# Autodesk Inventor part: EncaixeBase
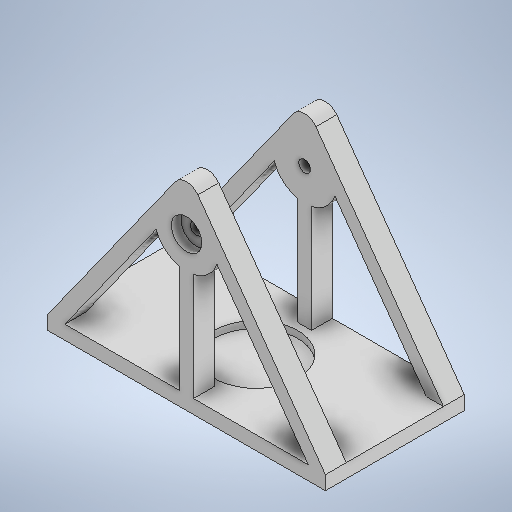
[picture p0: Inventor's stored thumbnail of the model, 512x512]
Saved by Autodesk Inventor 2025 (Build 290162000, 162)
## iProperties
Created: 2025-03
Part Number: EncaixeBase
Material: Genérico
Document SubType Name: Modeling
Designer: Ian
Density: 1 g/cm^3
Appearance: Padrão
Author: Ian
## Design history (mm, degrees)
sketch "Esboço1"
  geometry: L1 (-100, 5)-(100, 5); L2 (100, 5)-(100, -5); L3 (100, -5)-(-100, -5); L4 (-100, -5)-(-100, 5); L5 (-100, 5)-(100, -5); L6 (100, 5)-(-100, -5); 1 further point
  constraints: 12 end point, 2 midpoint, 2 parallel, 1 horizontal, 1 perpendicular
  dimensions: "d0" = 200 distance of L2.end L3.end; "d1" = 10 distance of L1.end L2.end
extrude "Extrusão1" new body sketch "Esboço1" distance "d2" = 100; taper "d3" = 0 deg
sketch "Esboço2"
  geometry: L1 (100, 5)-(-100, 5) reference; L2 (100, 5)-(-100, 5) reference; L3 (-100, -5)-(100, -5) reference; L4 (0, -5)-(0, 145); L5 (0, 145)-(-100, 5); L6 (0, 145)-(100, 5); 2 further points
  constraints: 6 end point, 2 midpoint, 1 vertical
  dimensions: "d20" = 150 distance of L4.start L4.end
extrude "Extrusão2" join sketch "Esboço2" distance "d7" = 15; taper "d8" = 0 deg
sketch "Esboço3"
  geometry: L1 (-100, 5)-(100, 5); L2 (100, -5)-(-100, -5) reference; L3 (0, -5)-(0, 145); L4 (-100, -5)-(-100, 5) reference; L5 (0, 145)-(-100, 5); L6 (0, 145)-(100, 5); 1 further point
  constraints: 8 end point, 1 midpoint, 1 vertical
  dimensions: "d21" = 150 distance of L3.start L3.end
extrude "Extrusão3" join sketch "Esboço3" distance "d9" = 15; taper "d10" = 0 deg
sketch "Esboço4"
  geometry: L1 (-100, -5)-(100, -5) reference; L2 (100, 5)-(0, 145) reference; L3 (0, 145)-(0, -5) reference; C1 r 4.25 at (0, 105); 1 further point
  constraints: 2 end point, 2 vertical, 1 centre point, 1 midpoint
  dimensions: "d13" = 8.5 diameter of C1; "d22" = 110 distance of L3.end C1.centre
extrude "Extrusão4" cut sketch "Esboço4" extent not by distance; stored distance "d14" = 0; taper "d15" = 0 deg
fillet "Arredondamento3" dims "d24" = 10
sketch "Esboço5"
  geometry: C1 r 4.25 at (0, 105) reference; C2 r 10.975 at (0, 105); 1 further point
  constraints: 1 centre point, 1 coincident
  dimensions: "d25" = 21.95 diameter of C2
extrude "Extrusão5" cut sketch "Esboço5" distance "d26" = 7; taper "d27" = 0 deg
sketch "Esboço6"
  geometry: C1 r 4.25 at (0, 105) reference; C2 r 10.975 at (0, 105); 1 further point
  constraints: 1 centre point, 1 coincident
  dimensions: "d28" = 21.95 diameter of C2
extrude "Extrusão6" cut sketch "Esboço6" distance "d29" = 7; taper "d30" = 0 deg
sketch "Esboço7"
  geometry: L1 (100, 5)-(8.137, 133.608) reference; L2 (21.886, 97.155)-(87.711, 5); L3 (100, 5)-(-100, 5) reference; L4 (87.711, 5)-(-87.711, 5); L5 (-21.886, 97.155)-(-87.711, 5); L6 (100, 5)-(8.137, 133.608) reference; L7 (-8.137, 133.608)-(-100, 5) reference; L8 (0, 105)-(0, -5.304) reference; L9 (5, 82.294)-(5, 5); L10 (-5, 82.294)-(-5, 5); C1 r 10.975 at (0, 105) reference; C2 r 4.25 at (0, 105) reference; A1 r 23.25 centre (0, 105) between (21.886, 97.155) and (-21.886, 97.155); 3 further points
  constraints: 12 end point, 4 parallel, 4 point on circle, 4 point on line, 2 vertical, 1 centre point, 1 coincident, 1 perpendicular, 1 tangent
  dimensions: "d31" = 10 distance between parallel lines of L1 L2; "d32" = 10 distance between parallel lines of L7 L5; "d39" = 5 distance between parallel lines of L9 L8; "d40" = 5 distance between parallel lines of L8 L10
extrude "Extrusão7" cut sketch "Esboço7" extent not by distance; stored distance "d33" = 0; taper "d34" = 0 deg
sketch "Esboço8"
  geometry: L1 (-200, 85)-(0, 85) reference; L2 (-108.137, -15)-(-200, -15) reference; L3 (0, 85)-(-200, 85); L4 (-200, 85)-(-200, -15); L5 (-200, -15)-(0, -15); L6 (0, -15)-(0, 85); L7 (0, 35)-(-200, 35); L8 (-100, -15)-(-100, 85); L9 (-91.863, 0)-(0, 0) reference; C1 r 30 at (-100, 35)
  constraints: 12 end point, 4 midpoint, 2 parallel, 2 perpendicular, 1 centre point, 1 horizontal
  dimensions: "d35" = 60 diameter of C1
extrude "Extrusão8" cut sketch "Esboço8" distance "d36" = 5; taper "d37" = 0 deg
node "Sólido1"
